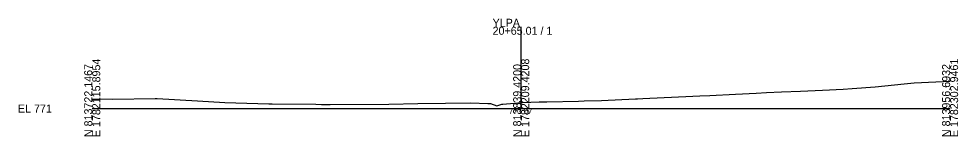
# Model space of a CAD drawing. Extents: x -76 to 1303, y -10 to 9544.
# Drawn here: x 974.3 to 1302.8, y 990.3 to 1031.5 of the extents above; entities that cross this region are included whole.
import ezdxf

# ---------------------------------------------------------------- set-up
doc = ezdxf.new("R2010")
doc.units = 0
for name, color, linetype in [('Exist Cross Section Cell', 7, 'Continuous'), ('Exist XS Center Line Elevation Label', 7, 'Continuous'), ('Exist XS Ground Line', 7, 'Continuous')]:
    doc.layers.add(name, color=color, linetype=linetype)

msp = doc.modelspace()

# ---------------------------------------------------------------- linework, layer by layer
at = {"layer": 'Exist Cross Section Cell'}
for p, q in [((1150, 1000), (1150, 1028.65)), ((1000, 1000), (1150, 1000)), ((1150, 1000), (1300, 1000))]:
    msp.add_line(p, q, dxfattribs=at)
at = {"layer": 'Exist XS Ground Line'}
for p, q in [((1273.79, 1007.64), (1283.91, 1008.69)), ((1283.91, 1008.69), (1287.4, 1009.04)), ((1287.4, 1009.04), (1294.98, 1009.37)), ((1294.98, 1009.37), (1300, 1009.55)), ((1225.01, 1005.03), (1232.19, 1005.41)), ((1232.19, 1005.41), (1235.81, 1005.61)), ((1235.81, 1005.61), (1241.03, 1005.85)), ((1241.03, 1005.85), (1247.63, 1006.12)), ((1247.63, 1006.12), (1255.35, 1006.45)), ((1255.35, 1006.45), (1262.65, 1006.79)), ((1262.65, 1006.79), (1265.73, 1007.05)), ((1265.73, 1007.05), (1273.79, 1007.64)), ((1000, 1003.38), (1007.17, 1003.32)), ((1007.17, 1003.32), (1022.05, 1003.5)), ((1022.05, 1003.5), (1022.67, 1003.5)), ((1022.67, 1003.5), (1036.76, 1002.66)), ((1036.76, 1002.66), (1046.35, 1002.16)), ((1046.35, 1002.16), (1061.8, 1001.62)), ((1147.58, 1001.91), (1148.88, 1002.05)), ((1148.88, 1002.05), (1150, 1002.07)), ((1150, 1002.07), (1150.42, 1002.07)), ((1150.42, 1002.07), (1156.33, 1002.3)), ((1156.33, 1002.3), (1158.94, 1002.33)), ((1158.94, 1002.33), (1170, 1002.64)), ((1170, 1002.64), (1172.04, 1002.69)), ((1172.04, 1002.69), (1178.04, 1002.84)), ((1178.04, 1002.84), (1189.93, 1003.43)), ((1189.93, 1003.43), (1190.71, 1003.46)), ((1190.71, 1003.46), (1192.53, 1003.54)), ((1192.53, 1003.54), (1210.03, 1004.32)), ((1210.03, 1004.32), (1212.47, 1004.44)), ((1212.47, 1004.44), (1216.01, 1004.59)), ((1216.01, 1004.59), (1225.01, 1005.03)), ((1061.8, 1001.62), (1062.92, 1001.6)), ((1062.92, 1001.6), (1078.23, 1001.52)), ((1078.23, 1001.52), (1080.19, 1001.46)), ((1080.19, 1001.46), (1083.18, 1001.47)), ((1083.18, 1001.47), (1103.68, 1001.53)), ((1103.68, 1001.53), (1113.91, 1001.77)), ((1113.91, 1001.77), (1123.59, 1001.93)), ((1123.59, 1001.93), (1132.42, 1002)), ((1132.42, 1002), (1138.32, 1001.81)), ((1138.32, 1001.81), (1139.25, 1001.77)), ((1139.25, 1001.77), (1141.44, 1000.92)), ((1141.44, 1000.92), (1143.21, 1001.51)), ((1143.21, 1001.51), (1143.61, 1001.58)), ((1143.61, 1001.58), (1147.58, 1001.91))]:
    msp.add_line(p, q, dxfattribs=at)

# ---------------------------------------------------------------- texts
at = {"layer": 'Exist Cross Section Cell'}
for s, p in [('YLPA', (1140, 1028.65)), ('20+65.01 / 1', (1140, 1025.85)), ('EL 771', (974, 998.6))]:
    msp.add_text(s, height=2.8, dxfattribs=at).set_placement(p)
for s, p in [('N 813722.1467', (1000, 990)), ('E 1782115.8954', (1002.8, 990)), ('N 813839.4200', (1150, 990)), ('E 1782209.4208', (1152.8, 990)), ('N 813956.6932', (1300, 990)), ('E 1782302.9461', (1302.8, 990))]:
    msp.add_text(s, height=2.8, rotation=90, dxfattribs=at).set_placement(p)
at = {"layer": 'Exist XS Center Line Elevation Label'}
msp.add_text('773.07', height=2, dxfattribs=at).set_placement((1145.7, 998.07))

doc.saveas('drawing.dxf')
